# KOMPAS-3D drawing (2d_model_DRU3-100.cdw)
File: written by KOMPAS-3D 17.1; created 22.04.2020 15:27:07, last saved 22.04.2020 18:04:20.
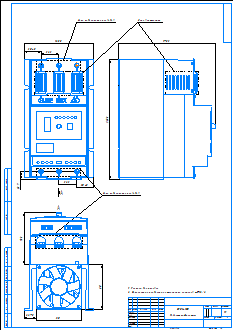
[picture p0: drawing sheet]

Sheet 1: A2, portrait

Title block, sheet 1: name: DRU3-100 / Габаритный чертеж; sheets: 1; sheet format: A2; stored path: E:\Марк\DRU3\DRU3-XX\2d_model_DRU3-100.cdw

Views: Вид по стрелке 3
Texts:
  Пользователь Windows
  HHT100ЙўИИЖч_40A
  100AµзБ¦µчХыЖчЙПёЗ(2014.5.12РЮёД)
  µзБ¦µчХыЖчРэЕҐ
Dimensions and other numbers on the sheet: 1:1; 1; 100AµзБ¦µчХыЖчєуЧщ; 100AµзБ¦µчХыЖчµЧЧщ; 100AµзБ¦µчХыЖчЅУПЯЧщ; 100AµзБ¦µчХыЖчЅУПЯЖ¬; 80·з»ъ; 100AµзБ¦µчХыЖч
